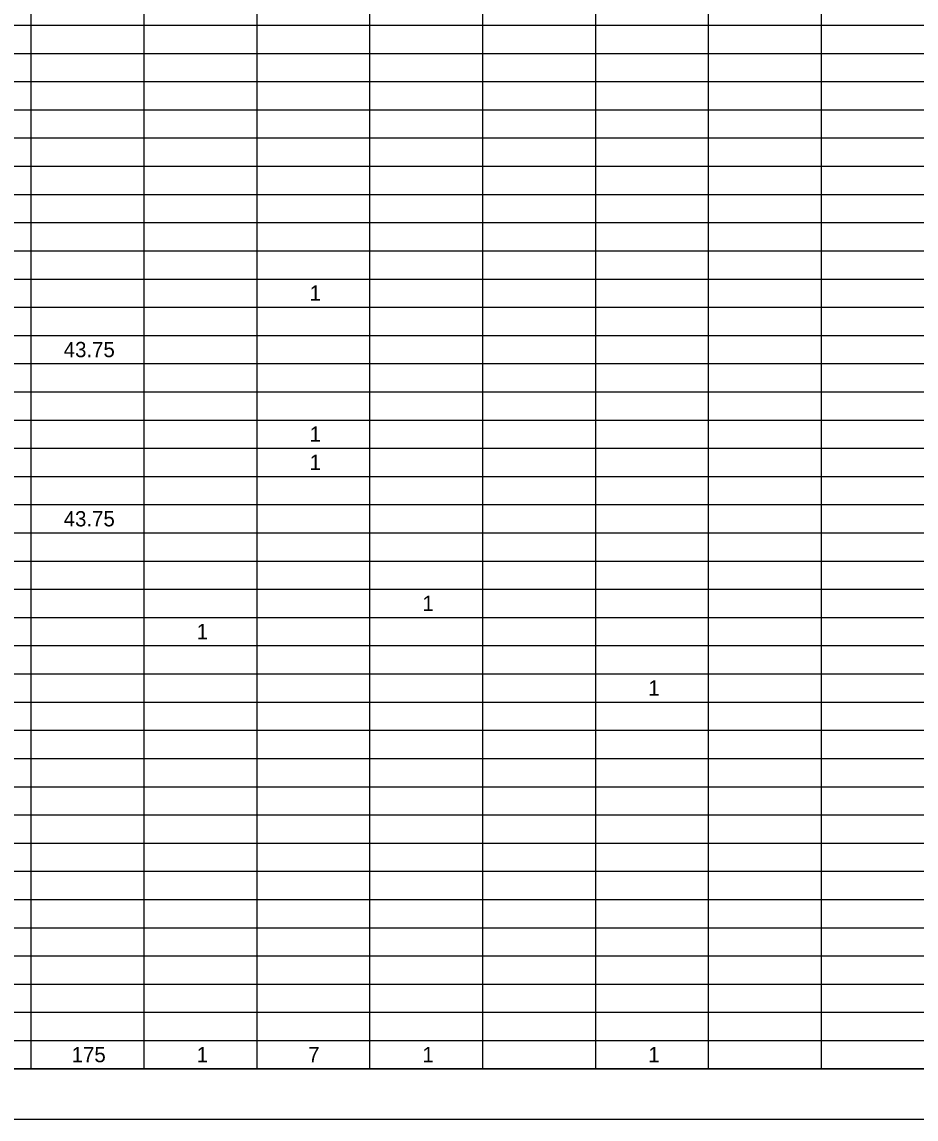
# Model space of a CAD drawing. Extents: x -0.1 to 36.2, y 0 to 22.
# Drawn here: x 18.34 to 27.21, y -0.02 to 10.87 of the extents above; entities that cross this region are included whole.
import ezdxf

# ---------------------------------------------------------------- set-up
doc = ezdxf.new("R2010")
doc.units = 0
for name, color, linetype in [('SH_Border', 7, 'Continuous'), ('SH_Cut_Line', 7, 'Continuous'), ('SH_Text', 7, 'Continuous')]:
    doc.layers.add(name, color=color, linetype=linetype)

msp = doc.modelspace()

# ---------------------------------------------------------------- linework, layer by layer
at = {"layer": 'SH_Border'}
msp.add_lwpolyline([(1.376, 21.475), (33.376, 21.475), (33.376, 0.475), (1.376, 0.475)], close=True, dxfattribs=at)
at = {"layer": 'SH_Cut_Line'}
msp.add_lwpolyline([(-0.124, -0.025), (33.876, -0.025), (33.876, 21.975), (-0.124, 21.975)], close=True, dxfattribs=at)
at = {"layer": 'SH_Text'}
for p, q in [((18.43, 21.475), (18.43, 0.475)), ((19.55, 21.475), (19.55, 0.475)), ((20.671, 21.475), (20.671, 0.475)), ((21.791, 21.475), (21.791, 0.475)), ((22.912, 21.475), (22.912, 0.475)), ((24.032, 21.475), (24.032, 0.475)), ((25.153, 21.475), (25.153, 0.475)), ((26.273, 21.475), (26.273, 0.475)), ((1.376, 10.835), (31.876, 10.835)), ((1.376, 10.555), (31.876, 10.555)), ((1.376, 10.275), (31.876, 10.275)), ((1.376, 9.995), (31.876, 9.995)), ((1.376, 9.715), (31.876, 9.715)), ((1.376, 9.435), (31.876, 9.435)), ((1.376, 9.155), (31.876, 9.155)), ((1.376, 8.875), (31.876, 8.875)), ((1.376, 8.595), (31.876, 8.595)), ((1.376, 8.315), (31.876, 8.315)), ((1.376, 8.035), (31.876, 8.035)), ((1.376, 7.755), (31.876, 7.755)), ((1.376, 7.475), (31.876, 7.475)), ((1.376, 7.195), (31.876, 7.195)), ((1.376, 6.915), (31.876, 6.915)), ((1.376, 6.635), (31.876, 6.635)), ((1.376, 6.355), (31.876, 6.355)), ((1.376, 6.075), (31.876, 6.075)), ((1.376, 5.795), (31.876, 5.795)), ((1.376, 5.515), (31.876, 5.515)), ((1.376, 5.235), (31.876, 5.235)), ((1.376, 4.955), (31.876, 4.955)), ((1.376, 4.675), (31.876, 4.675)), ((1.376, 4.395), (31.876, 4.395)), ((1.376, 4.115), (31.876, 4.115)), ((1.376, 3.835), (31.876, 3.835)), ((1.376, 3.555), (31.876, 3.555)), ((1.376, 3.275), (31.876, 3.275)), ((1.376, 2.995), (31.876, 2.995)), ((1.376, 2.715), (31.876, 2.715)), ((1.376, 2.435), (31.876, 2.435)), ((1.376, 2.155), (31.876, 2.155)), ((1.376, 1.875), (31.876, 1.875)), ((1.376, 1.595), (31.876, 1.595)), ((1.376, 1.315), (31.876, 1.315)), ((1.376, 1.035), (31.876, 1.035)), ((1.376, 0.755), (31.876, 0.755)), ((1.376, 0.475), (31.876, 0.475))]:
    msp.add_line(p, q, dxfattribs=at)

# ---------------------------------------------------------------- texts
for s, height, p in [('1', 0.152, (21.196, 8.099)), ('43.75', 0.1515, (18.756, 7.539)), ('1', 0.152, (21.196, 6.699)), ('1', 0.152, (21.196, 6.419)), ('43.75', 0.1515, (18.756, 5.859)), ('1', 0.152, (22.316, 5.019)), ('1', 0.152, (20.075, 4.739)), ('1', 0.152, (24.557, 4.179)), ('175', 0.1515, (18.835, 0.539)), ('1', 0.152, (20.075, 0.539)), ('7', 0.152, (21.182, 0.539)), ('1', 0.152, (22.316, 0.539)), ('1', 0.152, (24.557, 0.539))]:
    msp.add_text(s, height=height, dxfattribs=at).set_placement(p)

doc.saveas('drawing.dxf')
